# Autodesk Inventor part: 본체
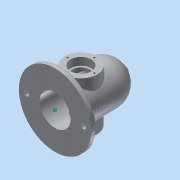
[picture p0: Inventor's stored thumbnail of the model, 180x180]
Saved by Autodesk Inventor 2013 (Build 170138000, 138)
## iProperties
Created: 2019-11
Part Number: 본체
Material: 알루미늄 6061
Document SubType Name: Modeling
Designer: Administrator
Density: 2.71 g/cm^3
Mass: 1110.43 g
Surface Area: 884.701 cm^2
Volume: 409.754 cm^3
Author: Administrator
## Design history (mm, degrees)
sketch "스케치1"
  geometry: 1 further point
sketch "스케치2"
  geometry: C1 r 70 at (0, 0); 1 further point
  constraints: 1 centre point, 1 coincident
  dimensions: "d0" = 140 diameter of C1
extrude "돌출1" new body sketch "스케치2" distance "d2" = 10; taper "d3" = 0 deg
sketch "스케치3"
  geometry: C1 r 70 at (0, 0) reference; C2 r 40 at (0, 0)
  constraints: 1 centre point, 1 coincident
  dimensions: "d4" = 80 diameter of C2
extrude "돌출2" join sketch "스케치3" distance "d6" = 80; taper "d7" = 0 deg
sketch "스케치4"
  geometry: L1 (0, 70)-(0, -70) reference; L2 (130, 0)-(50, 0); A1 r 40 centre (90, 0) between (130, 0) and (50, 0); 2 further points
  constraints: 2 end point, 2 point on circle, 1 centre point, 1 coincident, 1 perpendicular
  dimensions: "d8" = 90 distance from line of L1 point (90, 0); "d10" = 80 diameter of A1
revolve "회전1" sketch "스케치4" stored, may be unused: angle "d11" = 90 deg
sketch "스케치5"
  geometry: L1 (-70, 0)-(70, 0) reference; C1 r 31 at (0, 50); 2 further points
  constraints: 1 centre point, 1 coincident
  dimensions: "d12" = 50 distance from line of L1 point (0, 50); "d13" = 62 diameter of C1
extrude "돌출3" join sketch "스케치5" stored distance "d14" = 100; taper "d15" = 0 deg
node "작업 평면2"
sketch "스케치6"
  geometry: C1 r 7.5 at (0, 0); 1 further point
  constraints: 1 centre point, 1 coincident
  dimensions: "d18" = 15 diameter of C1
extrude "돌출4" join sketch "스케치6" stored distance "d20" = 100; taper "d21" = 0 deg
sketch "스케치7"
  geometry: C1 r 7.5 at (0, 0) reference; 1 further point
  constraints: 1 coincident
hole "구멍1" sketch "스케치7" at (0, 0) diameter "d22" = 5.188; stored, may be unused: countersink angle "d26" = 90 deg, drill point angle "d28" = 118 deg; dims "d23" = 6, "d24" = 4, "d25" = 2, "d27" = 8
fillet "모깎기1" dims "d29" = 3
sketch "스케치8"
  geometry: C1 r 31 at (0, 0) reference; C2 r 16.5 at (0, 0); 1 further point
  constraints: 1 centre point, 1 coincident
  dimensions: "d30" = 33 diameter of C2
extrude "돌출5" cut sketch "스케치8" distance "d32" = 100; taper "d33" = 0 deg
sketch "스케치9"
  geometry: C1 r 2.594 at (0, 0) reference; C2 r 70 at (0, 0) reference; C3 r 30 at (0, 0)
  constraints: 1 centre point, 1 coincident
  dimensions: "d34" = 60 diameter of C3
extrude "돌출6" cut sketch "스케치9" distance "d36" = 90; taper "d37" = 0 deg
sketch "스케치11"
  geometry: L1 (0, 70)-(0, -70) reference; L2 (60, 0)-(120, 0); A1 r 30 centre (90, 0) between (120, 0) and (60, 0); 2 further points
  constraints: 2 end point, 2 point on circle, 1 centre point, 1 coincident, 1 perpendicular
  dimensions: "d38" = 90 distance from line of L1 point (90, 0); "d39" = 60 diameter of A1
revolve "회전2" sketch "스케치11" stored, may be unused: angle "d40" = 90 deg
sketch "스케치12"
  geometry: C1 r 31 at (0, 0) reference; C2 r 20 at (0, 0); 1 further point
  constraints: 1 centre point, 1 coincident
  dimensions: "d41" = 40 diameter of C2
extrude "돌출7" cut sketch "스케치12" distance "d43" = 15; taper "d44" = 0 deg
sketch "스케치13"
  geometry: C1 r 31 at (0, 0) reference; C2 r 20 at (0, 0); 1 further point
  constraints: 1 centre point, 1 coincident
  dimensions: "d45" = 40 diameter of C2
extrude "돌출8" cut sketch "스케치13" distance "d47" = 15; taper "d48" = 0 deg
sketch "스케치14" dims "d49" = 52
  geometry: C1 r 31 at (0, 0) reference; C2 r 2 at (0, -26); 2 further points
  constraints: 2 vertical alignment, 1 centre point, 1 coincident, 2 other
  dimensions: "d51" = 4 diameter of C2
hole "구멍2" sketch "스케치14" at (0, -26) diameter "d52" = 3.242; stored, may be unused: countersink angle "d56" = 90 deg, drill point angle "d58" = 118 deg; dims "d53" = 8, "d54" = 4, "d55" = 2, "d57" = 10
sketch "스케치15" dims "d63" = 110
  geometry: C1 r 40 at (0, 0) reference; C2 r 70 at (0, 0) reference; C3 r 4.5 at (-55, 0); 1 further point
  constraints: 2 horizontal alignment, 1 centre point, 1 coincident, 2 other
  dimensions: "d62" = 9 diameter of C3
extrude "돌출9" cut sketch "스케치15" distance "d64" = 15; taper "d65" = 0 deg
node "작업 평면3"
sketch "스케치18"
  geometry: L1 (0, 70)-(0, -70) reference; 2 further points
  constraints: 1 horizontal alignment, 1 other
  dimensions: "d67" = 47.83 distance from line of L1 point (47.83, 0)
feature "엠보싱1" sketch "스케치18" dims "d12" = 50, "d13" = 62, "d68" = 0.5, "d69" = 0
fillet "모깎기2" dims "d70" = 3
fillet "모깎기3" dims "d71" = 3
fillet "모깎기4" dims "d72" = 3
fillet "모깎기5" dims "d73" = 0.3
node "솔리드1"
pattern_circular "원형 패턴1" dims angle "d60" = 360 deg
mirror "대칭1"
mirror "대칭2"
other parameters: "d17" = -135
